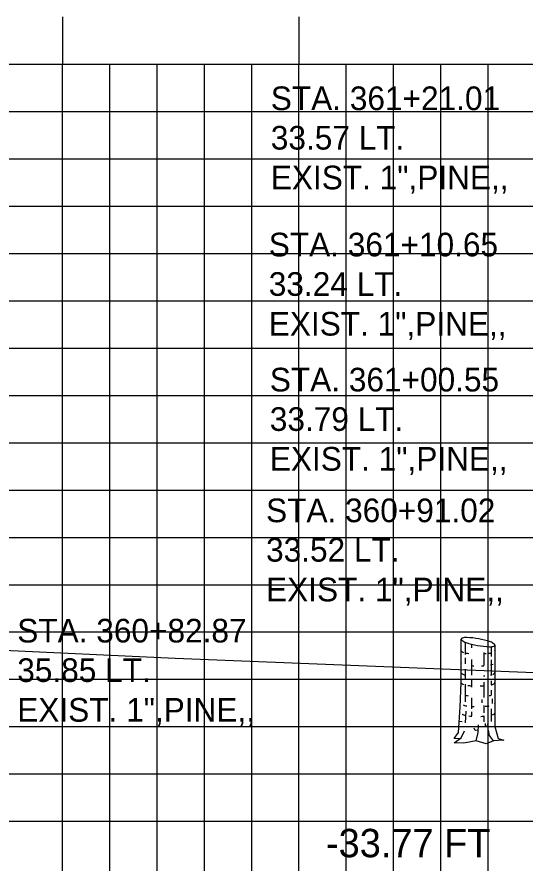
# Model space of a CAD drawing. Extents: x 1146525 to 1146695, y 608981 to 609091.
# Drawn here: x 1146561.7 to 1146572.45, y 609028.45 to 609046.34 of the extents above; entities that cross this region are included whole.
import ezdxf

# ---------------------------------------------------------------- set-up
doc = ezdxf.new("R2010")
doc.units = 0
for name, color, linetype in [('D_Text_Monospaced', 7, 'Continuous'), ('D_Text_Standard', 7, 'Continuous'), ('MAJOR', 7, 'Continuous'), ('MINOR', 7, 'Continuous'), ('S_Roadway_Centerline', 7, 'Continuous'), ('S_Trees_Conifer_NonPay', 7, 'Continuous')]:
    doc.layers.add(name, color=color, linetype=linetype)

msp = doc.modelspace()

# ---------------------------------------------------------------- linework, layer by layer
at = {"layer": 'MAJOR'}
for p, q in [((1146562.671, 609046.337), (1146562.671, 609045.335)), ((1146567.671, 609046.337), (1146567.671, 609045.335)), ((1146537.671, 609045.335), (1146677.671, 609045.335)), ((1146537.671, 609045.335), (1146677.671, 609045.335)), ((1146562.671, 609020.335), (1146562.671, 609045.335)), ((1146567.671, 609020.335), (1146567.671, 609045.335)), ((1146537.671, 609040.335), (1146677.671, 609040.335)), ((1146537.671, 609035.335), (1146677.671, 609035.335)), ((1146537.671, 609030.335), (1146677.671, 609030.335))]:
    msp.add_line(p, q, dxfattribs=at)
at = {"layer": 'MINOR'}
for p, q in [((1146563.671, 609020.335), (1146563.671, 609045.335)), ((1146564.671, 609020.335), (1146564.671, 609045.335)), ((1146565.671, 609020.335), (1146565.671, 609045.335)), ((1146566.671, 609020.335), (1146566.671, 609045.335)), ((1146568.671, 609020.335), (1146568.671, 609045.335)), ((1146569.671, 609020.335), (1146569.671, 609045.335)), ((1146570.671, 609020.335), (1146570.671, 609045.335)), ((1146571.671, 609020.335), (1146571.671, 609045.335)), ((1146537.671, 609044.335), (1146677.671, 609044.335)), ((1146537.671, 609043.335), (1146677.671, 609043.335)), ((1146537.671, 609042.335), (1146677.671, 609042.335)), ((1146537.671, 609041.335), (1146677.671, 609041.335)), ((1146537.671, 609039.335), (1146677.671, 609039.335)), ((1146537.671, 609038.335), (1146677.671, 609038.335)), ((1146537.671, 609037.335), (1146677.671, 609037.335)), ((1146537.671, 609036.335), (1146677.671, 609036.335)), ((1146537.671, 609034.335), (1146677.671, 609034.335)), ((1146537.671, 609033.335), (1146677.671, 609033.335)), ((1146537.671, 609032.335), (1146677.671, 609032.335)), ((1146537.671, 609031.335), (1146677.671, 609031.335)), ((1146537.671, 609029.335), (1146677.671, 609029.335))]:
    msp.add_line(p, q, dxfattribs=at)
at = {"layer": 'S_Roadway_Centerline'}
msp.add_lwpolyline([(1146557.189, 609033.149), (1146565.05, 609032.785), (1146581.825, 609032.109), (1146584.311, 609031.657), (1146589.374, 609030.827), (1146592.033, 609031.484), (1146593.468, 609031.837), (1146594.03, 609031.88), (1146595.014, 609031.905), (1146600.278, 609032.092), (1146606.448, 609032.182), (1146612.282, 609032.042), (1146617.286, 609031.872), (1146619.517, 609031.64), (1146621.574, 609031.449), (1146622.756, 609030.931), (1146624.182, 609030.468), (1146629.549, 609032.75), (1146635.043, 609035.129), (1146648.103, 609035.716), (1146654.911, 609035.417)], dxfattribs=at)
at = {"layer": 'S_Trees_Conifer_NonPay'}
for p, q in [((1146571.319, 609033.078), (1146571.319, 609033)), ((1146571.738, 609033.023), (1146571.738, 609032.818)), ((1146571.184, 609032.79), (1146571.184, 609032.659)), ((1146571.319, 609032.75), (1146571.319, 609032.425)), ((1146571.581, 609032.898), (1146571.581, 609032.625)), ((1146571.738, 609032.745), (1146571.738, 609032.414)), ((1146571.184, 609032.55), (1146571.184, 609032.324)), ((1146571.184, 609032.232), (1146571.184, 609031.856)), ((1146571.319, 609032.324), (1146571.319, 609032.17)), ((1146571.581, 609032.271), (1146571.581, 609031.953)), ((1146571.738, 609032.299), (1146571.738, 609032.221)), ((1146571.738, 609032.106), (1146571.738, 609031.997)), ((1146571.319, 609031.942), (1146571.319, 609031.708)), ((1146571.539, 609031.908), (1146571.539, 609031.839)), ((1146571.755, 609031.919), (1146571.755, 609031.822)), ((1146571.203, 609031.663), (1146571.186, 609031.418)), ((1146571.581, 609031.783), (1146571.581, 609031.624)), ((1146571.738, 609031.708), (1146571.738, 609031.44)), ((1146571.319, 609031.646), (1146571.319, 609031.56)), ((1146571.581, 609031.566), (1146571.581, 609031.435)), ((1146571.124, 609031.435), (1146571.064, 609031.441))]:
    msp.add_line(p, q, dxfattribs=at)
for points in [[(1146571.073, 609031.074), (1146570.957, 609031.083), (1146571.049, 609031.208), (1146571.083, 609031.749), (1146571.103, 609032.266), (1146571.103, 609033.185)], [(1146571.184, 609033.119), (1146571.184, 609033.022), (1146571.184, 609032.857)], [(1146571.816, 609033.057), (1146571.816, 609031.339), (1146571.886, 609031.083), (1146572.005, 609031.049), (1146571.789, 609031.032), (1146571.629, 609030.974), (1146571.42, 609031.032), (1146571.157, 609030.985), (1146570.951, 609030.991), (1146571.103, 609031.094), (1146571.175, 609031.248)], [(1146571.467, 609031.258), (1146571.397, 609031.253), (1146571.379, 609031.305)], [(1146571.42, 609031.032), (1146571.465, 609031.208), (1146571.47, 609031.373)], [(1146571.657, 609031.395), (1146571.669, 609031.351), (1146571.618, 609031.339), (1146571.618, 609031.401)], [(1146571.789, 609031.032), (1146571.699, 609031.145), (1146571.682, 609031.259)]]:
    msp.add_lwpolyline(points, dxfattribs=at)
for centre, radius, start, end in [((1146571.117, 609033.183), 0.0141, 153.567, 169.6202), ((1146571.117, 609033.183), 0.0141, 169.6202, 185.6733), ((1146571.122, 609033.183), 0.0186, 185.6733, 199.6202), ((1146571.129, 609033.186), 0.0263, 199.6202, 218.3805), ((1146571.121, 609033.181), 0.0186, 139.6202, 153.567), ((1146571.127, 609033.176), 0.0263, 120.8598, 139.6202), ((1146571.166, 609033.215), 0.0729, 218.3805, 229.6202), ((1146571.151, 609033.136), 0.0729, 109.6202, 120.8598), ((1146571.277, 609033.346), 0.245, 229.6202, 251.6054), ((1146571.209, 609032.974), 0.245, 87.6349, 109.6202), ((1146571.776, 609034.846), 1.825, 251.6054, 259.6202), ((1146571.144, 609031.395), 1.825, 79.6202, 87.6349), ((1146571.144, 609031.395), 1.825, 71.6054, 79.6202), ((1146571.642, 609032.894), 0.245, 49.6202, 71.6054), ((1146571.121, 609032.943), 0.0189, 196.0515, 210), ((1146571.128, 609032.947), 0.0267, 210, 228.7494), ((1146571.159, 609032.982), 0.0738, 228.7494, 240), ((1146571.245, 609033.13), 0.245, 240, 248.2347), ((1146571.776, 609034.846), 1.825, 259.6202, 267.6349), ((1146571.711, 609033.267), 0.245, 267.6349, 289.6202), ((1146571.768, 609033.104), 0.0729, 289.6202, 300.8598), ((1146571.754, 609033.025), 0.0729, 38.3805, 49.6202), ((1146571.792, 609033.064), 0.0263, 300.8598, 319.6202), ((1146571.79, 609033.054), 0.0263, 19.6202, 38.3805), ((1146571.798, 609033.059), 0.0186, 319.6202, 333.567), ((1146571.798, 609033.057), 0.0186, 5.6733, 19.6202), ((1146571.802, 609033.057), 0.0141, 333.567, 349.6202), ((1146571.801, 609032.942), 0.0143, 343.9485, 360), ((1146571.802, 609033.057), 0.0141, 349.6202, 5.6733), ((1146571.245, 609033.13), 0.245, 255.8141, 261.8968), ((1146571.459, 609034.638), 1.767, 261.8968, 263.7551), ((1146571.459, 609034.638), 1.767, 273.9501, 275.6733), ((1146571.459, 609034.638), 1.767, 277.395, 278.1032), ((1146571.674, 609033.13), 0.245, 278.1032, 285.1539), ((1146571.12, 609032.691), 0.0189, 196.0515, 210), ((1146571.126, 609032.695), 0.0267, 210, 228.7494), ((1146571.457, 609034.385), 1.767, 265.5153, 267.2779), ((1146571.457, 609034.385), 1.767, 272.4038, 274.1009), ((1146571.672, 609032.878), 0.245, 282.4625, 295.6852), ((1146571.121, 609032.477), 0.0189, 196.0515, 210), ((1146571.128, 609032.481), 0.0267, 210, 228.7494), ((1146571.159, 609032.516), 0.0738, 228.7494, 240), ((1146571.245, 609032.664), 0.245, 240, 255.8141), ((1146571.459, 609034.172), 1.767, 273.8675, 274.7715), ((1146571.674, 609032.664), 0.245, 282.4546, 285.1539), ((1146571.674, 609032.664), 0.245, 293.2086, 300), ((1146571.759, 609032.516), 0.0738, 300, 311.2506), ((1146571.79, 609032.481), 0.0267, 311.2506, 330), ((1146571.797, 609032.477), 0.0189, 330, 343.9485), ((1146571.801, 609032.476), 0.0143, 343.9485, 360), ((1146571.121, 609032.265), 0.0189, 196.0515, 210), ((1146571.128, 609032.269), 0.0267, 210, 228.7494), ((1146571.159, 609032.305), 0.0738, 228.7494, 240), ((1146571.244, 609032.453), 0.245, 240, 247.8076), ((1146571.459, 609033.96), 1.767, 262.9974, 265.4639), ((1146571.459, 609033.96), 1.767, 271.4475, 273.9571), ((1146571.674, 609032.453), 0.245, 285.0486, 300), ((1146571.759, 609032.305), 0.0738, 300, 311.2506), ((1146571.79, 609032.269), 0.0267, 311.2506, 330), ((1146571.797, 609032.265), 0.0189, 330, 343.9485), ((1146571.801, 609032.264), 0.0143, 343.9485, 360), ((1146571.245, 609032.233), 0.245, 255.6793, 261.8968), ((1146571.46, 609033.741), 1.767, 261.8968, 263.2034), ((1146571.46, 609033.741), 1.767, 277.55, 278.1032), ((1146571.674, 609032.233), 0.245, 278.1032, 285.0186), ((1146571.245, 609032.016), 0.245, 245.3944, 261.8968), ((1146571.46, 609033.524), 1.767, 261.8968, 262.37), ((1146571.46, 609033.524), 1.767, 265.4388, 267.3707), ((1146571.46, 609033.524), 1.767, 274.9504, 277.7378), ((1146571.802, 609031.828), 0.0143, 343.9485, 360), ((1146571.16, 609031.663), 0.0738, 237.95, 240), ((1146571.246, 609031.81), 0.245, 240, 255.9316), ((1146571.46, 609033.318), 1.767, 263.6994, 265.7224), ((1146571.46, 609033.318), 1.767, 271.7813, 273.9138), ((1146571.675, 609031.81), 0.245, 290.8325, 300), ((1146571.76, 609031.663), 0.0738, 300, 311.2506), ((1146571.791, 609031.627), 0.0267, 311.2506, 330), ((1146571.798, 609031.623), 0.0189, 330, 343.9485), ((1146571.803, 609031.622), 0.0143, 343.9485, 360)]:
    msp.add_arc(centre, radius, start, end, dxfattribs=at)

# ---------------------------------------------------------------- texts
at = {"layer": 'D_Text_Monospaced'}
for s, height, p in [('STA. 361+21.01', 0.49998, (1146567.075, 609044.367)), ('33.57 LT.', 0.5, (1146567.075, 609043.533)), ('EXIST. 1",PINE,,', 0.49998, (1146567.075, 609042.693)), ('STA. 361+10.65', 0.49998, (1146567.032, 609041.275)), ('33.24 LT.', 0.5, (1146567.032, 609040.441)), ('EXIST. 1",PINE,,', 0.49998, (1146567.032, 609039.601)), ('STA. 361+00.55', 0.49998, (1146567.054, 609038.42)), ('33.79 LT.', 0.5, (1146567.054, 609037.586)), ('EXIST. 1",PINE,,', 0.49998, (1146567.054, 609036.746)), ('STA. 360+91.02', 0.49998, (1146566.975, 609035.656)), ('33.52 LT.', 0.5, (1146566.975, 609034.822)), ('EXIST. 1",PINE,,', 0.49998, (1146566.975, 609033.982)), ('STA. 360+82.87', 0.49998, (1146561.711, 609033.113)), ('35.85 LT.', 0.5, (1146561.711, 609032.279)), ('EXIST. 1",PINE,,', 0.49998, (1146561.711, 609031.439))]:
    msp.add_text(s, height=height, dxfattribs=at).set_placement(p)
at = {"layer": 'D_Text_Standard'}
msp.add_text('-33.77 FT', height=0.6, dxfattribs=at).set_placement((1146568.243, 609028.573))

doc.saveas('drawing.dxf')
